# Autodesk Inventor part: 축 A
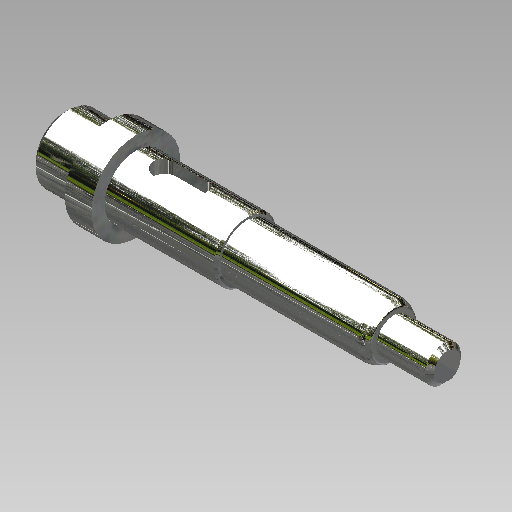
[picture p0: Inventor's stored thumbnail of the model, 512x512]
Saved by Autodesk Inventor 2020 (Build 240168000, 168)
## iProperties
Created: 2020-04
Part Number: 축 A
Material: 알루미늄 6061
Document SubType Name: Modeling
Designer: mduedu
Density: 2.7 g/cm^3
Mass: 31.3085 g
Surface Area: 41.2026 cm^2
Volume: 11.5958 cm^3
Appearance: 알루미늄 - 평지
Author: mduedu
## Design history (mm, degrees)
sketch "스케치1"
  geometry: L1 (0, 0)-(10, 0); L2 (10, 0)-(10, 7.5); L3 (10, 7.5)-(0, 7.5); L4 (0, 7.5)-(0, 0); L5 (10, 0)-(16, 0); L6 (16, 0)-(16, 10); L7 (16, 10)-(10, 10); L8 (10, 10)-(10, 0); L9 (16, 0)-(41, 0); L10 (41, 0)-(41, 7); L11 (41, 7)-(16, 7); L12 (16, 7)-(16, 0); L13 (41, 0)-(74, 0); L14 (74, 0)-(74, 6); L15 (74, 6)-(41, 6); L16 (41, 6)-(41, 0); L17 (74, 0)-(86, 0); L18 (86, 0)-(86, 4); L19 (86, 4)-(74, 4); L20 (74, 4)-(74, 0)
  constraints: 40 end point, 10 parallel, 5 horizontal, 5 perpendicular
  dimensions: "d0" = 86 distance between parallel lines of L18 L4; "d2" = 10 distance of L2.end L3.end; "d3" = 6 distance of L6.end L7.end; "d4" = 12 distance of L18.end L19.end; "d5" = 8 diameter of L19 L17; "d6" = 12 diameter of L15 L13; "d7" = 14 diameter of L11 L9; "d8" = 15 diameter of L3 L1; "d9" = 20 diameter of L7 L5; "d10" = 45 distance between parallel lines of L10 L18
revolve "회전1" sketch "스케치1" stored, may be unused: angle "d11" = 90 deg
sketch "스케치2"
  geometry: L1 (0, -7.5)-(0, 7.5) reference; L2 (0, 7.5)-(10, 7.5) reference; L3 (10, 7.5)-(10, 10) reference; L4 (10, 10)-(16, 10) reference; L5 (16, 10)-(16, 7) reference; L6 (16, 7)-(41, 7) reference; L7 (41, 7)-(41, 6) reference; L8 (41, 6)-(74, 6) reference; L9 (74, 6)-(74, 4) reference; L10 (74, 4)-(86, 4) reference; L11 (86, 4)-(86, -4) reference; L12 (86, -4)-(74, -4) reference; L13 (74, -4)-(74, -6) reference; L14 (74, -6)-(41, -6) reference; L15 (41, -6)-(41, -7) reference; L16 (41, -7)-(16, -7) reference; L17 (16, -7)-(16, -10) reference; L18 (16, -10)-(10, -10) reference; L19 (10, -10)-(10, -7.5) reference; L20 (10, -7.5)-(0, -7.5) reference; L21 (86, -4)-(78, -4); L22 (78, -4)-(78, -2.8); L23 (78, -2.8)-(86, -2.8); L24 (86, -2.8)-(86, -4); 1 further point
  constraints: 8 end point, 2 parallel, 1 horizontal, 1 perpendicular
  dimensions: "d12" = 8 distance of L22.end L23.end; "d13" = 1.2 distance of L21.end L22.end
extrude "돌출1" cut sketch "스케치2" stored distance "d14" = 2; taper "d15" = 0 deg
fillet "모깎기1" dims "d16" = 1
sketch "스케치3"
  geometry: L1 (0, -7.5)-(0, 7.5) reference; L2 (0, 7.5)-(10, 7.5) reference; L3 (10, 7.5)-(10, 10) reference; L4 (10, 10)-(16, 10) reference; L5 (16, 10)-(16, 7) reference; L6 (16, 7)-(41, 7) reference; L7 (41, 7)-(41, 6) reference; L8 (41, 6)-(74, 6) reference; L9 (74, 6)-(74, 4) reference; L10 (74, 4)-(86, 4) reference; L11 (86, 4)-(86, -2.8) reference; L12 (86, -2.8)-(78, -2.8) reference; L13 (78, -2.8)-(78, -4) reference; L14 (78, -4)-(74, -4) reference; L15 (74, -4)-(74, -6) reference; L16 (74, -6)-(41, -6) reference; L17 (41, -6)-(41, -7) reference; L18 (41, -7)-(16, -7) reference; L19 (16, -7)-(16, -10) reference; L20 (16, -10)-(10, -10) reference; L21 (10, -10)-(10, -7.5) reference; L22 (10, -7.5)-(0, -7.5) reference; L23 (20, 7)-(32, 7); L24 (32, 7)-(32, 4); L25 (32, 4)-(20, 4); L26 (20, 4)-(20, 7); 1 further point
  constraints: 8 end point, 2 parallel, 1 horizontal, 1 perpendicular, 1 point on line
  dimensions: "d17" = 12 distance of L24.end L25.end; "d18" = 3 distance of L23.end L24.end; "d19" = 4 distance from line of L26 L4.end
extrude "돌출2" cut sketch "스케치3" stored distance "d20" = 5; taper "d21" = 0 deg
fillet "모깎기2" dims "d22" = 2.5
chamfer "모따기1" distance "d23" = 1; stored, may be unused: second distance "d24" = 2, angle "d25" = 45 deg
chamfer "모따기2" distance "d26" = 0.5; stored, may be unused: second distance "d27" = 2, angle "d28" = 45 deg
fillet "모깎기3" dims "d29" = 0.3
chamfer "모따기3" distance "d30" = 1.56; stored, may be unused: second distance "d31" = 2, angle "d32" = 30 deg
fillet "모깎기4" dims "d33" = 4, "d34" = 0.5
node "솔리드1"
node "절단 모서리 투영1"
node "절단 모서리 투영2"
